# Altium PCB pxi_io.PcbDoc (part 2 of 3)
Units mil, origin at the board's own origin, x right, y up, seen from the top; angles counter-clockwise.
Board outline 6300 x 3935 mil, 2 copper layers (Top Layer, Bottom Layer); 271 components, 388 nets, 1544 pads, 249 vias.
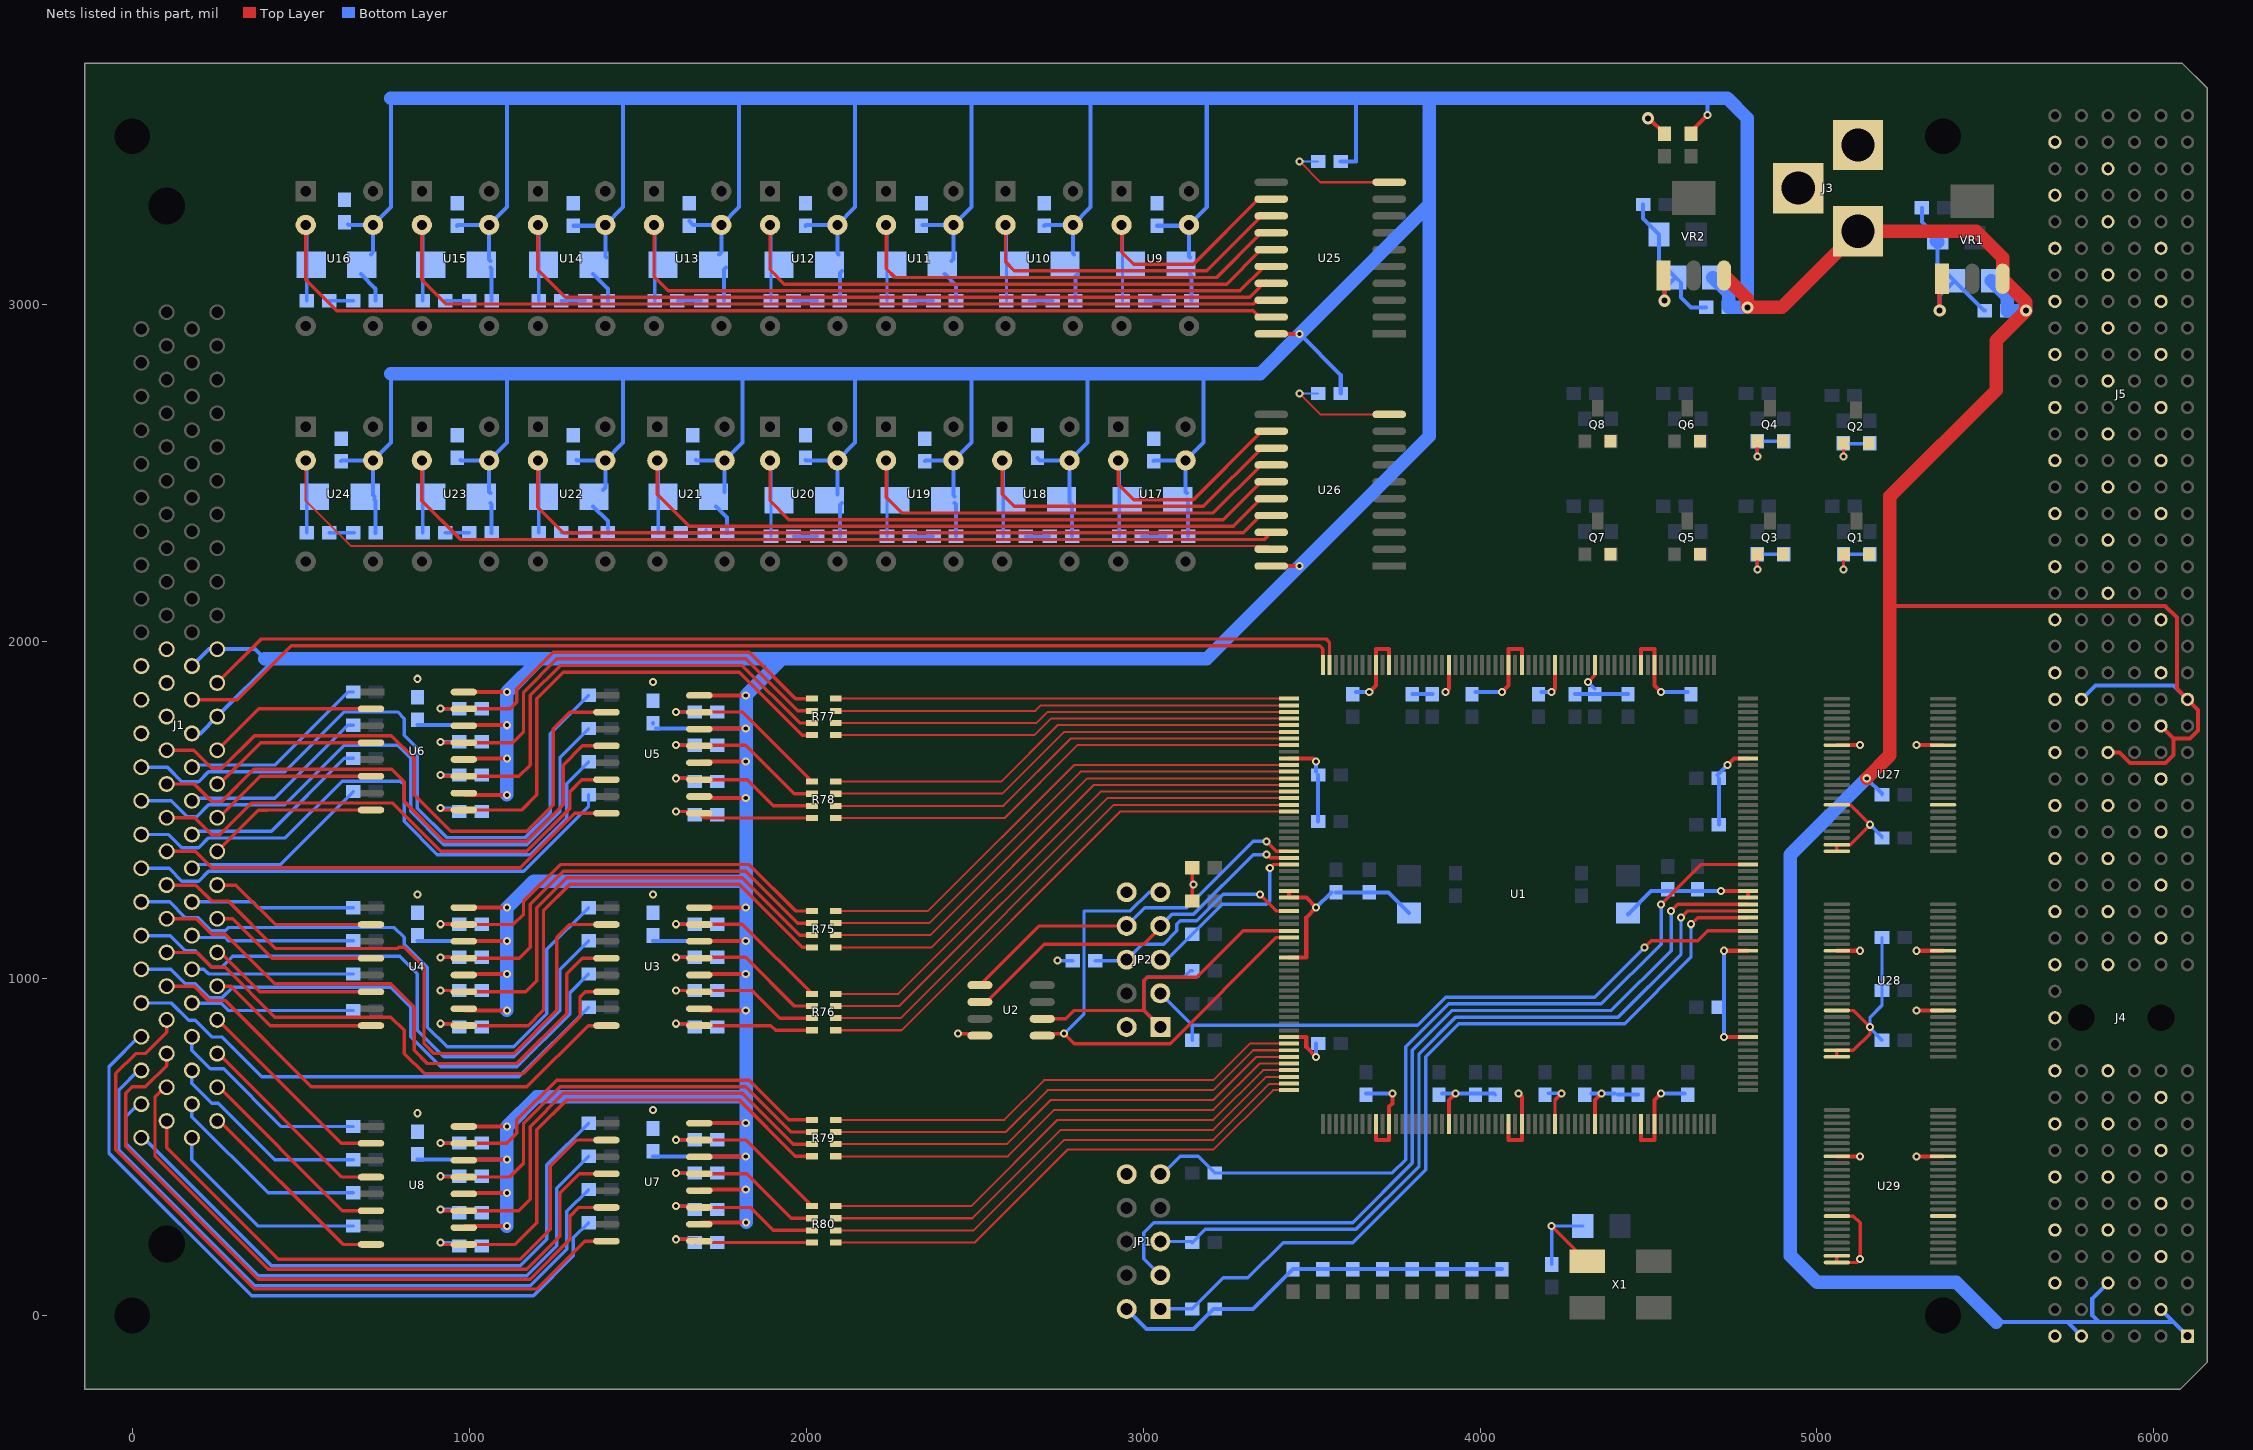
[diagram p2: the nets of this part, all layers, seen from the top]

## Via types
v1: diameter 24, hole 12, Top Layer to Bottom Layer, 241 vias
v2: diameter 36, hole 18, Top Layer to Bottom Layer, 7 vias
v3: diameter 24, hole 12, Top Layer to Bottom Layer, tented bottom, 1 vias

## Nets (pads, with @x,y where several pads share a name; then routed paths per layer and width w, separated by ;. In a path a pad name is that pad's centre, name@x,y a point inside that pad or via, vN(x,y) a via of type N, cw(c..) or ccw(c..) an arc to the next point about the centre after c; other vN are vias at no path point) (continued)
5V: C51.2 C52.2 C53.2 C54.2 C55.2 C56.2 C91.2 C92.2 C93.2 C94.2 C95.2 C96.2 C97.2 C98.2 C99.2 C101.2 C102.2 C103.2 C104.2 C105.2 C106.2 C107.2 C108.2 C109.2 C111.1 C112.2 C115.1 C116.2 D1.2 D2.2 D3.2 D4.2 D5.2 D6.2 D7.2 D8.2 D11.2 D12.2 D13.2 D14.2 D15.2 D16.2 D17.2 D18.2 D19.1 DS9.1 J1.25 J1.26 J1.29 J1.30 J3.1 J4.A1 J4.A25 J4.B2 J4.B24 J4.D3 J4.D23 J4.E1 J4.E25 R81.2 R82.2 R83.2 R84.2 R85.2 R86.2 R87.2 R88.2 R91.2 R92.2 R93.2 R94.2 R95.2 R96.2 R97.2 R98.2 U3.10 U3.12 U3.14 U3.16 U4.10 U4.12 U4.14 U4.16 U5.10 U5.12 U5.14 U5.16 U6.10 U6.12 U6.14 U6.16 U7.10 U7.12 U7.14 U7.16 U8.10 U8.12 U8.14 U8.16 U9.9 U10.9 U11.9 U12.9 U13.9 U14.9 U15.9 U16.9 U17.9 U18.9 U19.9 U20.9 U21.9 U22.9 U23.9 U24.9 U25.20 U26.20 VR1.3 VR2.3 | length 41262.1
  Top Layer w10: DS9.1@4625.98,3507.87 DS9.1@4625.98,3513.78
  Top Layer w12: U8.10@984.25,261.02 988.98,265.75 v1(1112.2,265.75) ; U8.12@984.25,361.02 987.4,364.17 v1(1112.2,364.17) ; U8.14@984.25,461.02 985.83,462.6 v1(1112.2,462.6) ; U8.16@984.25,561.02 v1(1112.2,561.02) ; U4.10@984.25,910.63 989.37,905.51 v1(1112.2,905.51) ; U4.12@984.25,1010.63 987.4,1013.78 v1(1112.2,1013.78) ; U4.14@984.25,1110.63 985.83,1112.2 v1(1112.2,1112.2) ; U4.16@984.25,1210.63 v1(1112.2,1210.63) ; U6.10@984.25,1550.39 989.37,1545.28 v1(1112.2,1545.28) ; U6.12@984.25,1650.39 987.4,1653.54 v1(1112.2,1653.54) ; U6.16@984.25,1850.39 v1(1112.2,1850.39) ; U6.14@985.83,1751.97 v1(1112.2,1751.97) ; U7.10@1683.07,270.87 1688.77,276.57 v1(1821.84,276.57) ; U7.12@1683.07,370.87 1686.22,374.02 v1(1820.87,374.02) ; U7.16@1683.07,570.87 v1(1820.87,570.87) ; U3.10@1683.07,910.63 1688.19,905.51 v1(1820.87,905.51) ; U3.12@1683.07,1010.63 1686.22,1013.78 v1(1820.87,1013.78) ; U3.14@1683.07,1110.63 1684.65,1112.2 v1(1820.87,1112.2) ; U3.16@1683.07,1210.63 v1(1820.87,1210.63) ; U5.10@1683.07,1540.55 1688.19,1535.43 v1(1820.87,1535.43) ; U5.12@1683.07,1640.55 1686.22,1643.7 v1(1820.87,1643.7) ; U5.14@1683.07,1740.55 1684.65,1742.13 v1(1820.87,1742.13) ; U5.16@1683.07,1840.55 v1(1820.87,1840.55) ; U7.14@1684.65,472.44 v1(1820.87,472.44) ; U26.20@3380.31,2224.41 v1(3464.57,2224.41) ; U25.20@3380.31,2913.39 v1(3464.57,2913.39) ; DS9.1@4625.98,3513.78 v1(4675.2,3562.99) ; 5216.54,2106.3 6033.46,2106.3 6067.92,2071.84 6067.92,1860.43 J4.A25@6099.61,1828.74 6131.29,1797.06 6131.29,1736.88 6107.01,1712.6 6058.27,1712.6 ; J4.D23@5863.39,1671.26 5897.32,1671.26 5929,1639.57 6033.99,1639.57 6058.27,1663.85 6058.27,1712.6 ; J4.B24@6020.87,1750 6058.27,1712.6
  Top Layer w40: VR2.3@4724.04,3086.61 4793.31,3017.35 v2(4793.31,2992.13) 4895.93,2992.13 J3.1@5121.74,3217.94 5472.27,3217.94 5550.81,3139.39 VR1.3@5550.81,3076.77 5620.08,3007.5 v2(5620.08,2982.28) 5531.5,2893.7 5531.5,2746.06 5216.54,2431.1 5216.54,2106.3 5216.54,1663.39 v1(5147.64,1594.49)
  Bottom Layer w10: D19.1@5192.91,1545.28 D19.1@5192.91,1549.21 ; v2@5610.24,2982.28 v2(5620.08,2982.28)
  Bottom Layer w12: J1.25@177.17,1727.56 202.17,1727.56 J1.26@252.17,1777.56 423.23,1948.62 ; J1.29@177.17,1927.56 227.95,1978.35 252.17,1978.35 364.17,1978.35 393.7,1948.82 393.7,1942.72 ; C108.2@620.08,2535.43 622.44,2537.8 U24.9@714.96,2537.8 ; C98.2@639.76,3238.19 641.34,3236.61 U16.9@714.96,3236.61 ; D8.2@679.13,3090.55 722.44,3047.24 R88.2@722.44,3011.81 ; D8.2@708.66,3149.61 714.96,3155.91 U16.9@714.96,3236.61 ; D18.2@718.5,2421.26 722.44,2417.32 R98.2@722.44,2322.83 ; D18.2@718.5,2431.1 714.96,2434.65 U24.9@714.96,2537.8 ; 767.72,2795.28 767.72,2590.55 U24.9@714.96,2537.8 ; 767.72,3612.2 767.72,3289.37 U16.9@714.96,3236.61 ; C56.2@846.46,462.6 v1(1112.2,462.6) ; C52.2@846.46,1112.2 v1(1112.2,1112.2) ; C54.2@846.46,1751.97 v1(1112.2,1751.97) ; C97.2@964.57,3234.25 966.93,3236.61 U15.9@1059.45,3236.61 ; C107.2@974.41,2539.37 975.98,2537.8 U23.9@1059.45,2537.8 ; D17.2@1062.99,2411.42 1066.93,2407.48 R97.2@1066.93,2322.83 ; D17.2@1062.99,2440.94 1059.45,2444.49 U23.9@1059.45,2537.8 ; D7.2@1062.99,3110.24 1066.93,3106.3 R87.2@1066.93,3011.81 ; D7.2@1062.99,3129.92 1059.45,3133.47 U15.9@1059.45,3236.61 ; 1112.2,2795.28 1112.2,2590.55 U23.9@1059.45,2537.8 ; 1112.2,3612.2 1112.2,3289.37 U15.9@1059.45,3236.61 ; C96.2@1309.06,3234.25 1401.57,3234.25 U14.9@1403.94,3236.61 ; C106.2@1318.9,2539.37 1320.47,2537.8 U22.9@1403.94,2537.8 ; D16.2@1368.11,2401.57 1411.42,2358.27 R96.2@1411.42,2322.83 ; D6.2@1368.11,3090.55 1411.42,3047.24 R86.2@1411.42,3011.81 ; D16.2@1397.64,2450.79 1403.94,2457.09 U22.9@1403.94,2537.8 ; D6.2@1407.48,3139.76 1403.94,3143.31 U14.9@1403.94,3236.61 ; 1456.69,2795.28 1456.69,2590.55 U22.9@1403.94,2537.8 ; 1456.69,3612.2 1456.69,3289.37 U14.9@1403.94,3236.61 ; C55.2@1545.28,472.44 v1(1820.87,472.44) ; C51.2@1545.28,1112.2 v1(1820.87,1112.2) ; C53.2@1555.12,1742.13 v1(1820.87,1742.13) v1@1821.84,1742.13 ; C95.2@1653.54,3248.03 1664.96,3236.61 U13.9@1748.43,3236.61 ; C105.2@1673.23,2539.37 1674.8,2537.8 U21.9@1758.27,2537.8 ; D15.2@1732.28,2401.57 1765.75,2368.11 R95.2@1765.75,2322.83 ; D5.2@1742.13,3149.61 1748.43,3155.91 U13.9@1748.43,3236.61 ; R85.2@1755.91,3011.81 1755.91,3104.33 D5.2@1761.81,3110.24 ; D15.2@1758.27,2444.49 U21.9@1758.27,2537.8 ; 1801.18,3612.2 1801.18,3289.37 U13.9@1748.43,3236.61 ; 1811.02,2795.28 1811.02,2590.55 U21.9@1758.27,2537.8 ; C104.2@1998.03,2539.37 1999.61,2537.8 U20.9@2092.91,2537.8 ; C94.2@1998.03,3234.25 2000.39,3236.61 U12.9@2092.91,3236.61 ; D14.2@2092.91,2437.4 U20.9@2092.91,2537.8 ; D4.2@2096.46,3149.61 2092.91,3153.15 U12.9@2092.91,3236.61 ; R94.2@2100.39,2312.99 2100.39,2405.51 D14.2@2106.3,2411.42 ; R84.2@2100.39,3011.81 2100.39,3094.49 D4.2@2106.3,3100.39 ; 2145.67,2795.28 2145.67,2590.55 U20.9@2092.91,2537.8 ; 2145.67,3612.2 2145.67,3289.37 U12.9@2092.91,3236.61 ; C93.2@2344.88,3236.61 U11.9@2437.4,3236.61 ; C103.2@2352.36,2535.43 2354.72,2537.8 U19.9@2437.4,2537.8 ; D3.2@2411.42,3090.55 2444.88,3057.09 R83.2@2444.88,3011.81 ; D3.2@2431.1,3129.92 2437.4,3136.22 U11.9@2437.4,3236.61 ; D13.2@2440.94,2411.42 2444.88,2407.48 R93.2@2444.88,2312.99 ; D13.2@2440.94,2431.1 2437.4,2434.65 U19.9@2437.4,2537.8 ; 2490.16,2795.28 2490.16,2590.55 U19.9@2437.4,2537.8 ; 2490.16,3612.2 2490.16,3289.37 U11.9@2437.4,3236.61 ; C102.2@2687.01,2545.28 2694.49,2537.8 U18.9@2781.89,2537.8 ; C92.2@2706.69,3234.25 2709.06,3236.61 U10.9@2791.73,3236.61 ; R92.2@2789.37,2312.99 2789.37,2407.48 2781.89,2414.96 U18.9@2781.89,2537.8 ; D2.2@2795.28,3149.61 2791.73,3153.15 U10.9@2791.73,3236.61 ; R82.2@2799.21,3011.81 2799.21,3084.65 D2.2@2805.12,3090.55 ; 2834.65,2795.28 2834.65,2590.55 U18.9@2781.89,2537.8 ; 2844.49,3612.2 2844.49,3289.37 U10.9@2791.73,3236.61 ; C101.2@3031.5,2535.43 3033.86,2537.8 U17.9@3126.38,2537.8 ; C91.2@3041.34,3234.25 3133.86,3234.25 U9.9@3136.22,3236.61 ; D11.2@3129.92,2421.26 3133.86,2417.32 R91.2@3133.86,2312.99 ; D11.2@3129.92,2440.94 3126.38,2444.49 U17.9@3126.38,2537.8 ; D1.2@3139.76,3090.55 3143.7,3086.61 R81.2@3143.7,3011.81 ; D1.2@3139.76,3139.76 3136.22,3143.31 U9.9@3136.22,3236.61 ; 3179.13,2795.28 3179.13,2590.55 U17.9@3126.38,2537.8 ; 3188.98,3612.2 3188.98,3289.37 U9.9@3136.22,3236.61 ; v1(3464.57,2913.39) 3465.05,2912.9 3586.61,2791.34 C109.2@3586.61,2736.22 ; C99.2@3586.61,3425.2 3631.89,3425.2 3631.89,3612.2 ; v1(4675.2,3562.99) 4675.2,3612.2 ; v1(5147.64,1594.49) D19.1@5192.91,1549.21 ; 5531.5,-19.68 5743.31,-19.68 ; J4.E1@5784.65,-61.02 5743.31,-19.68 ; J4.E25@5784.65,1828.74 5825.98,1870.08 6058.27,1870.08 J4.A25@6099.61,1828.74 ; J4.D3@5863.39,96.46 5816.93,50 5816.93,0 5836.61,-19.68 ; 5984.25,-18.9 5984.25,-19.68 ; J4.B2@6020.87,17.72 6058.27,-19.68 ; J4.A1@6099.61,-61.02 6058.27,-19.68 ; 5743.31,-19.68 5836.61,-19.68 ; 5836.61,-19.68 5984.25,-19.68 ; 5984.25,-19.68 6058.27,-19.68
  Bottom Layer w40: 393.7,1948.82 1210.63,1948.82 ; 767.72,2795.28 1112.2,2795.28 1456.69,2795.28 1811.02,2795.28 2145.67,2795.28 2490.16,2795.28 2834.65,2795.28 3179.13,2795.28 3347.43,2795.28 3465.05,2912.9 3849.4,3297.24 ; 767.72,3612.2 1112.2,3612.2 1456.69,3612.2 1801.18,3612.2 2145.67,3612.2 2490.16,3612.2 2844.49,3612.2 3188.98,3612.2 3849.4,3612.2 ; v1(1112.2,265.75) v1(1112.2,462.6) v1(1112.2,561.02) 1200.79,649.61 1821.84,649.61 ; v1(1112.2,905.51) v1(1112.2,1013.78) v1(1112.2,1112.2) v1(1112.2,1210.63) 1190.94,1289.37 1821.84,1289.37 ; v1(1112.2,1545.28) v1(1112.2,1653.54) v1(1112.2,1751.97) v1(1112.2,1850.39) 1210.63,1948.82 ; v1(1821.84,276.57) 1821.84,472.44 1821.84,649.61 ; C115.1@4690.94,3080.71 4738.19,3033.46 C116.2@4738.19,2992.13 v2(4793.31,2992.13) 4793.31,3553.15 4734.25,3612.2 3849.4,3612.2 ; v1(5147.64,1594.49) 4921.26,1368.11 4921.26,177.17 5000,98.43 5413.39,98.43 5531.5,-19.68 ; C111.1@5517.72,3070.87 5564.96,3023.62 C112.2@5564.96,2982.28 v2(5620.08,2982.28) ; 1210.63,1948.82 1929.13,1948.82 ; 1821.84,649.61 1821.84,1289.37 ; 1821.84,1289.37 1821.84,1742.13 1821.84,1841.53 1929.13,1948.82 ; 1929.13,1948.82 3188.98,1948.82 3849.4,2609.24 3849.4,3297.24 ; 3849.4,3297.24 3849.4,3612.2
ASDO: JP2.9 U1.37 U2.5 | length 1506.9
  Top Layer w10: U2.5@2706.89,836.61 v3(2765.75,836.61) 2795.28,807.09 3080.71,807.09 3395.67,1122.05 U1.37@3433.07,1122.05
  Bottom Layer w10: v3(2765.75,836.61) 2824.8,895.67 2824.8,1200.79 2962.6,1200.79 3018.11,1256.3 JP2.9@3051.18,1256.3
CONF_DONE: JP2.3 R6.2 U1.145 | length 1944.1
  Top Layer w10: v1(4488.19,1092.52) 4507.87,1112.2 4645.67,1112.2 4675.2,1141.73 U1.145@4795.28,1141.73
  Bottom Layer w10: JP2.3@3051.18,956.3 3145.67,861.81 ; R6.2@3145.67,816.93 3145.67,861.81 ; v1(4488.19,1092.52) 4340.55,944.88 3897.64,944.88 3814.57,861.81 3145.67,861.81
DATA: JP2.7 U1.25 U2.2 | length 1105.4
  Top Layer w10: U2.2@2515.75,930.51 2534.84,930.51 2706.69,1102.36 3001.97,1102.36 3051.18,1151.57 JP2.7@3051.18,1156.3 ; v1(3366.14,1368.11) 3375.98,1358.27 U1.25@3433.07,1358.27
  Bottom Layer w10: JP2.7@3051.18,1156.3 3085.83,1190.94 3149.61,1190.94 3326.77,1368.11 v1(3366.14,1368.11)
DC5_CTRL: J1.27 U1.240 | length 3474.2
  Top Layer w10: J1.27@177.17,1827.56 311.81,1827.56 472.44,1988.19 3523.62,1988.19 3533.46,1978.35 U1.240@3533.46,1931.1
DC27_CTRL: J1.28 U1.239 | length 3426
  Top Layer w10: J1.28@252.17,1877.56 382.48,2007.87 3543.31,2007.87 3553.15,1998.03 U1.239@3553.15,1931.1
DCLK: JP2.1 R5.2 U1.36 U2.6 | length 1276.1
  Top Layer w10: U2.6@2700.79,880.51 2770.28,880.51 2795.28,905.51 3001.97,905.51 ; JP2.1@3051.18,856.3 3001.97,905.51 ; U1.36@3433.07,1141.73 3297.24,1141.73 3159.45,1003.94 3011.81,1003.94 3001.97,994.09 3001.97,905.51
  Bottom Layer w10: JP2.1@3051.18,856.3 3001.97,905.51 3001.97,994.09 3011.81,1003.94 3120.08,1003.94 3139.76,1023.62 R5.2@3145.67,1023.62
GND: C1.2 C2.1 C3.2 C5.1 C6.1 C7.2 C9.1 C10.1 C11.1 C12.1 C13.1 C14.1 C15.1 C16.1 C17.1 C18.1 C19.1 C20.1 C21.1 C22.1 C31.1 C32.1 C33.1 C34.1 C35.1 C36.1 C37.1 C38.1 C39.1 C40.1 C41.1 C42.1 C51.1 C52.1 C53.1 C54.1 C55.1 C56.1 C91.1 C92.1 C93.1 C94.1 C95.1 C96.1 C97.1 C98.1 C99.1 C101.1 C102.1 C103.1 C104.1 C105.1 C106.1 C107.1 C108.1 C109.1 C111.2 C112.1 C113.2 C114.1 C115.2 C116.1 C117.2 C118.1 C120.1 C121.1 C123.1 J1.75 J1.76 J1.77 J1.78 J1.79 J1.80 J3.2 J3.3 J4.B4 J4.B6 J4.B8 J4.B10 J4.B16 J4.B18 J4.B20 J4.B22 J4.D5 J4.D7 J4.D9 J4.D11 J4.D15 J4.D17 J4.D19 J4.D21 J4.F1 J4.F3 J4.F5 J4.F7 J4.F9 J4.F11 J4.F13 J4.F15 J4.F17 J4.F19 J4.F21 J4.F23 J4.F25 J5.B1 J5.B3 J5.B7 J5.B9 J5.B11 J5.B13 J5.B15 J5.B17 J5.D4 J5.D6 J5.D8 J5.D10 J5.D12 J5.D14 J5.D16 J5.D18 J5.D20 J5.F1 J5.F3 J5.F5 J5.F7 J5.F9 J5.F11 J5.F13 J5.F15 J5.F17 J5.F19 J5.F21 JP1.2 JP1.10 JP2.2 JP2.10 Q1.3 Q2.3 Q3.3 Q4.3 Q5.3 Q6.3 Q7.3 Q8.3 R3.2 R4.1 R9.2 R10.2 R15.2 R16.2 R17.2 R18.2 R23.2 R24.2 R25.2 R26.2 R31.2 R32.2 R33.2 R34.2 R39.2 R40.2 R41.2 R42.2 R55.2 R56.2 R57.2 R58.2 R71.2 R72.2 R73.2 R74.2 R116.1 R120.2 R121.2 R122.2 R123.2 R124.2 R125.2 R126.2 R127.2 R140.1 U1.10 U1.30 U1.31 U1.40 U1.52 U1.69 U1.71 U1.80 U1.89 U1.91 U1.96 U1.102 U1.109 U1.111 U1.129 U1.142 U1.150 U1.151 U1.171 U1.190 U1.192 U1.199 U1.205 U1.210 U1.212 U1.221 U1.230 U1.232 U2.4 U25.10 U26.10 U27.8 U27.17 U27.32 U27.41 U27.47 U27.48 U28.8 U28.17 U28.32 U28.41 U28.47 U28.48 U29.8 U29.17 U29.32 U29.41 U29.47 U29.48 VR1.1 VR2.1 X1.2 | length 10385.4
  Top Layer w6: v1(3464.57,2736.22) 3526.38,2674.41 U26.10@3730.31,2674.41 ; v1(3464.57,3425.2) 3526.38,3363.39 U25.10@3730.31,3363.39
  Top Layer w10: v1(2450.79,836.61) 2509.65,836.61 U2.4@2515.75,830.51 ; R10.2@3145.67,1230.32 3145.67,1275.59 v1(3149.61,1279.53) 3145.67,1283.46 R9.2@3145.67,1328.74 ; v1(4212.6,265.75) 4317.24,161.1 X1.2@4318.13,161.1 ; U1.96@4222.44,568.9 4222.44,639.76 v1(4242.13,659.45) ; v1(4320.87,1879.92) 4340.55,1899.61 U1.199@4340.55,1931.1 ; J3.3@4904.64,3385.83 J3.3@4944.57,3345.89 ; U29.47@5059.06,177.17 U29.48@5059.06,157.48 5118.11,157.48 v1(5127.95,167.32) 5127.95,275.59 5108.27,295.28 U29.41@5059.06,295.28 ; U28.48@5059.06,767.72 U28.47@5059.06,787.4 5108.27,787.4 5157.48,836.61 v1(5157.48,856.3) 5108.27,905.51 U28.41@5059.06,905.51 ; U27.48@5059.06,1377.95 U27.47@5059.06,1397.64 5098.43,1397.64 v1(5157.48,1456.69) 5118.11,1496.06 ; U27.41@5059.06,1515.75 5098.43,1515.75 5118.11,1496.06 ; 5119.08,1497.03 5118.11,1496.06
  Top Layer w12: U1.52@3433.07,826.77 3484.25,826.77 3484.25,797.24 v1(3513.78,767.72) ; U1.40@3433.07,1062.99 3484.25,1062.99 3484.25,1181.1 v1(3513.78,1210.63) 3484.25,1240.16 U1.31@3433.07,1240.16 U1.30@3433.07,1259.84 ; U1.10@3433.07,1653.54 3503.94,1653.54 v1(3513.78,1643.7) ; v1(3671.26,1850.39) 3690.94,1870.08 U1.232@3690.94,1931.1 3690.94,1978.35 3730.31,1978.35 U1.230@3730.31,1931.1 ; U1.69@3690.94,568.9 3690.94,521.65 3730.31,521.65 U1.71@3730.31,568.9 3730.31,620.08 3740.16,629.92 v1(3740.16,659.45) ; v1(3897.64,1850.39) 3907.48,1860.24 U1.221@3907.48,1931.1 ; U1.80@3907.48,568.9 3907.48,639.76 v1(3927.17,659.45) ; v1(4064.96,1850.39) 4084.65,1870.08 U1.212@4084.65,1931.1 4084.65,1978.35 4124.02,1978.35 U1.210@4124.02,1931.1 ; U1.89@4084.65,568.9 4084.65,521.65 4124.02,521.65 U1.91@4124.02,568.9 4124.02,649.61 v1(4114.17,659.45) ; v1(4212.6,1850.39) 4222.44,1860.24 U1.205@4222.44,1931.1 ; U1.102@4340.55,568.9 4340.55,639.76 v1(4360.24,659.45) ; U1.109@4478.35,568.9 4478.35,521.65 4517.72,521.65 U1.111@4517.72,568.9 4517.72,639.76 v1(4537.4,659.45) ; U1.192@4478.35,1931.1 4478.35,1978.35 4517.72,1978.35 U1.190@4517.72,1931.1 4517.72,1870.08 v1(4537.4,1850.39) ; v2(4498.03,3553.15) 4501.97,3553.15 R140.1@4547.24,3507.87 ; v2(4547.24,3011.81) VR2.1@4547.24,3051.18 ; v1(4714.57,1259.84) U1.151@4795.28,1259.84 U1.150@4795.28,1240.16 ; v1(4724.41,826.77) U1.129@4795.28,826.77 ; v1(4724.41,1082.68) U1.142@4795.28,1082.68 ; v1(4734.25,1633.86) 4753.94,1653.54 U1.171@4795.28,1653.54 ; U29.32@5059.06,472.44 v1(5127.95,472.44) ; U28.32@5059.06,1082.68 v1(5127.95,1082.68) ; U27.32@5059.06,1692.91 v1(5127.95,1692.91) ; v1(5295.28,472.44) U29.17@5374.02,472.44 ; v1(5295.28,905.51) U28.8@5374.02,905.51 ; v1(5295.28,1082.68) U28.17@5374.02,1082.68 ; v1(5295.28,1692.91) U27.17@5374.02,1692.91 ; v2(5364.17,2982.28) VR1.1@5364.17,3070.13
  Top Layer w40: J3.2@5121.74,3467.57 J3.2@5121.74,3473.84
  Bottom Layer w6: v1(3464.57,2736.22) C109.1@3519.69,2736.22 ; v1(3464.57,3425.2) C99.1@3519.69,3425.2
  Bottom Layer w10: v1(2746.06,1053.15) R4.1@2791.34,1053.15 ; C18.1@4041.34,659.45 C18.1@4045.28,655.51 ; C38.1@4202.76,659.45 v1(4242.13,659.45) ; C2.1@4212.6,151.57 v1(4212.6,265.75) C1.2@4305.12,265.75 ; v1(4320.87,1879.92) C15.1@4340.55,1860.24 ; C115.2@4580.71,3080.71 C115.2@4596.46,3064.96 ; v1(5157.48,1456.69) 5192.91,1421.26 R116.1@5192.91,1417.32 ; C120.1@5192.91,816.93 5157.48,852.36 v1(5157.48,856.3) 5157.48,885.83 5192.91,921.26 C121.1@5192.91,964.57 C123.1@5192.91,1122.05 ; C111.2@5407.48,3070.87 C111.2@5423.23,3055.12
  Bottom Layer w12: JP1.2@2951.18,19.68 3010.24,-39.37 3149.61,-39.37 3208.66,19.68 R3.2@3212.6,19.68 3326.77,19.68 R127.2@3444.88,137.8 R126.2@3533.46,137.8 R125.2@3622.05,137.8 R124.2@3710.63,137.8 R123.2@3799.21,137.8 R122.2@3887.8,137.8 R121.2@3976.38,137.8 R120.2@4064.96,137.8 ; v1(3513.78,767.72) C40.1@3513.78,807.09 ; v1(3513.78,1210.63) C6.1@3559.06,1255.91 ; C42.1@3513.78,1614.17 v1(3513.78,1643.7) ; C41.1@3519.69,1466.54 C42.1@3519.69,1604.33 ; C6.1@3572.83,1255.91 C5.1@3671.26,1255.91 3728.35,1255.91 C3.2@3789.37,1194.88 ; C31.1@3631.89,1850.39 v1(3671.26,1850.39) ; C39.1@3661.42,659.45 v1(3740.16,659.45) ; C11.1@3799.21,1844.49 C12.1@3858.27,1844.49 ; C17.1@3887.8,659.45 v1(3927.17,659.45) C18.1@4041.34,659.45 ; C13.1@3986.22,1850.39 v1(4064.96,1850.39) ; C32.1@4183.07,1850.39 v1(4212.6,1850.39) ; C14.1@4281.5,1844.49 C15.1@4340.55,1844.49 C16.1@4438.98,1844.49 ; 4330.71,659.45 v1(4360.24,659.45) C21.1@4399.61,659.45 ; C21.1@4409.45,655.51 C22.1@4468.5,655.51 ; C7.2@4438.98,1190.94 4507.87,1259.84 v1(4714.57,1259.84) ; C118.1@4484.25,3297.24 4484.25,3255.91 C117.2@4531.5,3208.66 4531.5,3129.92 C115.2@4580.71,3080.71 4547.24,3047.24 v2(4547.24,3011.81) ; v1(4537.4,659.45) C37.1@4606.3,659.45 ; v1(4537.4,1850.39) C33.1@4616.14,1850.39 ; C115.2@4596.46,3064.96 4596.46,3021.65 4625.98,2992.13 C116.1@4671.26,2992.13 ; C34.1@4704.72,1604.33 v1(4734.25,1633.86) ; C35.1@4708.66,1456.69 C34.1@4708.66,1594.49 ; v1(4724.41,826.77) 4724.41,905.51 v1(4724.41,1082.68) ; C114.1@5311.02,3287.4 5311.02,3246.06 C113.2@5358.27,3198.82 ; C113.2@5358.27,3185.04 5358.27,3120.08 C111.2@5407.48,3070.87 ; v2(5364.17,2982.28) 5364.17,3027.56 C111.2@5407.48,3070.87 ; C112.1@5498.03,2982.28 5496.06,2982.28 C111.2@5407.48,3070.87
  Bottom Layer w40: J3.2@5121.74,3473.84 J3.2@5124.58,3473.84 ; C113.2@5354.33,3188.98 C113.2@5358.27,3185.04
  other v1: 846.46,600.39 1545.28,610.24 846.46,1250 1545.28,1250 1545.28,1879.92 846.46,1889.76
GND_I5_1: J1.60 U3.8 | length 1504.1
  Top Layer w10: J1.60@102.17,977.56 183.86,977.56 226.38,935.04 275.59,935.04 531.5,679.13 1171.26,679.13 1352.76,860.63 U3.8@1407.48,860.63
GND_I5_2: J1.62 U3.6 | length 1629.3
  Top Layer w10: J1.62@102.17,1077.56 192.13,1077.56 236.22,1033.46 275.59,1033.46 423.23,885.83 767.72,885.83 807.09,846.46 807.09,777.56 866.14,718.5 1161.42,718.5 1328.74,885.83 1328.74,944.88 1344.49,960.63 U3.6@1407.48,960.63
GND_I5_3: J1.64 U3.4 | length 1756.9
  Top Layer w10: J1.64@102.17,1177.56 190.55,1177.56 236.22,1131.89 275.59,1131.89 423.23,984.25 767.72,984.25 836.61,915.35 836.61,787.4 875.98,748.03 1141.73,748.03 1289.37,895.67 1289.37,1013.78 1336.22,1060.63 U3.4@1407.48,1060.63
GND_I5_4: J1.66 U3.2 | length 1933.3
  Top Layer w10: J1.66@102.17,1277.56 188.98,1277.56 236.22,1230.32 285.43,1230.32 426.54,1089.2 787.09,1089.2 790.4,1092.52 807.09,1092.52 866.14,1033.46 866.14,807.09 895.67,777.56 1131.89,777.56 1259.84,905.51 1259.84,1122.05 1298.43,1160.63 U3.2@1407.48,1160.63
GND_I5_5: J1.10 U4.8 | length 504.9
  Top Layer w10: J1.10@252.17,977.56 292.13,977.56 409.05,860.63 U4.8@708.66,860.63
GND_I5_6: J1.12 U4.6 | length 502.3
  Top Layer w10: J1.12@256.59,1081.99 377.95,960.63 U4.6@708.66,960.63
GND_I5_7: J1.14 U4.4 | length 504.9
  Top Layer w10: J1.14@252.17,1177.56 298.82,1177.56 415.75,1060.63 U4.4@708.66,1060.63
GND_I5_8: J1.16 U4.2 | length 504.9
  Top Layer w10: J1.16@252.17,1277.56 307.09,1277.56 424.02,1160.63 U4.2@708.66,1160.63
GND_I5_9: J1.68 U5.8 | length 1392.6
  Top Layer w10: J1.68@102.17,1377.56 187.4,1377.56 236.22,1328.74 1151.57,1328.74 1313.39,1490.55 U5.8@1407.48,1490.55
GND_I5_10: J1.70 U5.6 | length 1541.4
  Top Layer w10: J1.70@102.17,1477.56 185.83,1477.56 236.22,1427.17 260.26,1427.17 354.33,1521.24 772.07,1521.24 915.35,1377.95 1171.26,1377.95 1299.21,1505.91 1299.21,1555.12 1334.65,1590.55 U5.6@1407.48,1590.55
GND_I5_11: J1.72 U5.4 | length 1676
  Top Layer w10: J1.72@102.17,1577.56 184.25,1577.56 236.22,1525.59 265.75,1525.59 361.39,1621.24 770.5,1621.24 807.09,1584.65 807.09,1525.59 925.2,1407.48 1171.26,1407.48 1279.53,1515.75 1279.53,1633.86 1336.22,1690.55 U5.4@1407.48,1690.55
GND_I5_12: J1.74 U5.2 | length 1828
  Top Layer w10: J1.74@102.17,1677.56 182.68,1677.56 236.22,1624.02 265.75,1624.02 362.97,1721.24 768.92,1721.24 836.61,1653.54 836.61,1545.28 944.88,1437.01 1171.26,1437.01 1250,1515.75 1250,1742.13 1298.43,1790.55 U5.2@1407.48,1790.55
GND_I5_13: J1.18 U6.8 | length 507.4
  Top Layer w10: J1.18@252.17,1377.56 374.35,1499.75 400.33,1499.75 400.97,1500.39 U6.8@708.66,1500.39
GND_I5_14: J1.20 U6.6 | length 508.8
  Top Layer w10: J1.20@249.7,1480.02 259.55,1480.02 379.92,1600.39 U6.6@708.66,1600.39
GND_I5_15: J1.22 U6.4 | length 500.9
  Top Layer w10: J1.22@258.66,1577.56 381.5,1700.39 U6.4@708.66,1700.39
GND_I5_16: J1.24 U6.2 | length 507.4
  Top Layer w10: J1.24@252.17,1677.56 375,1800.39 U6.2@708.66,1800.39
GND_I27_1: J1.58 U7.8 | length 2152.2
  Top Layer w10: J1.58@102.17,877.56 102.17,840.35 39.37,777.56 9.84,777.56 -49.21,718.5 -49.21,492.13 364.17,78.74 1200.79,78.74 1342.91,220.87 U7.8@1407.48,220.87
GND_I27_2: J1.56 U7.6 | length 2067.8
  Top Layer w10: J1.56@102.17,777.56 102.17,741.93 39.37,679.13 0,679.13 -19.68,659.45 -19.68,501.97 374.02,108.27 1181.1,108.27 1299.21,226.38 1299.21,295.28 1324.8,320.87 U7.6@1407.48,320.87
GND_I27_3: J1.54 U7.4 | length 1894.7
  Top Layer w10: J1.54@102.17,682.87 67.54,648.25 67.54,473.8 403.54,137.8 1171.26,137.8 1269.68,236.22 1269.68,364.17 1326.38,420.87 U7.4@1407.48,420.87
GND_I27_4: J1.52 U7.2 | length 1777.7
  Top Layer w10: J1.52@102.17,577.56 102.17,498.23 433.07,167.32 1151.57,167.32 1240.16,255.91 1240.16,442.91 1318.11,520.87 U7.2@1407.48,520.87
GND_I27_5: J1.2 U8.8 | length 611.2
  Top Layer w10: J1.2@252.17,584.45 625.59,211.02 U8.8@708.66,211.02
GND_I27_6: J1.4 U8.6 | length 610.5
  Top Layer w10: J1.4@252.17,682.87 624.02,311.02 U8.6@708.66,311.02
GND_I27_7: J1.6 U8.4 | length 609.9
  Top Layer w10: J1.6@252.17,781.3 622.44,411.02 U8.4@708.66,411.02
GND_I27_8: J1.8 U8.2 | length 609.2
  Top Layer w10: J1.8@252.17,879.72 620.87,511.02 U8.2@708.66,511.02
I5_1: J1.59 R11.1 | length 1503.5
  Bottom Layer w10: J1.59@27.17,927.56 115.75,927.56 167.32,875.98 187.01,875.98 236.22,826.77 265.75,826.77 383.86,708.66 1147.64,708.66 R11.1@1354.33,915.35
I5_2: J1.61 R12.1 | length 1676
  Bottom Layer w10: J1.61@27.17,1027.56 114.17,1027.56 157.48,984.25 187.01,984.25 228.32,942.94 266.51,942.94 297.98,974.41 767.72,974.41 826.77,915.35 826.77,826.77 915.35,738.19 1141.73,738.19 1299.21,895.67 1299.21,958.66 R12.1@1354.33,1013.78
I5_3: J1.63 R13.1 | length 1815.8
  Bottom Layer w10: J1.63@27.17,1127.56 112.6,1127.56 157.48,1082.68 187.01,1082.68 236.22,1033.46 265.75,1033.46 298.84,1066.56 793.68,1066.56 846.46,1013.78 846.46,846.46 925.2,767.72 1131.89,767.72 1269.68,905.51 1269.68,1027.56 R13.1@1354.33,1112.2
I5_4: J1.65 R14.1 | length 1912
  Bottom Layer w10: J1.65@27.17,1227.56 111.02,1227.56 157.48,1181.1 195.46,1181.1 234.83,1141.73 275.59,1141.73 285.43,1151.57 777.56,1151.57 807.09,1122.05 807.09,1102.36 875.98,1033.46 875.98,856.3 935.04,797.24 1131.89,797.24 1230.32,895.67 1230.32,1086.61 R14.1@1354.33,1210.63
I5_5: J1.9 R19.1 | length 487.5
  Bottom Layer w10: J1.9@177.17,927.56 177.79,926.94 264.01,926.94 285.43,905.51 R19.1@655.51,905.51
I5_6: J1.11 R20.1 | length 484.9
  Bottom Layer w10: J1.11@177.79,1026.94 J1.11@177.17,1027.56 212.6,1027.56 226.38,1013.78 R20.1@655.51,1013.78
I5_7: J1.13 R21.1 | length 484.7
  Bottom Layer w10: J1.13@177.17,1127.56 182.68,1122.05 275.59,1122.05 285.43,1112.2 R21.1@655.51,1112.2
I5_8: J1.15 R22.1 | length 485.4
  Bottom Layer w10: J1.15@177.17,1227.56 357.09,1227.56 374.02,1210.63 R22.1@655.51,1210.63
I5_9: J1.67 R27.1 | length 1468.6
  Bottom Layer w10: J1.67@27.17,1327.56 109.45,1327.56 147.64,1289.37 196.85,1289.37 226.38,1318.9 1161.42,1318.9 1354.33,1511.81 R27.1@1354.33,1545.28
I5_10: J1.69 R28.1 | length 1753.4
  Bottom Layer w10: J1.69@27.17,1427.56 107.87,1427.56 147.64,1387.8 196.85,1387.8 226.38,1417.32 454.38,1417.32 622.86,1585.8 796.09,1585.8 807.09,1574.8 807.09,1466.54 905.51,1368.11 1181.1,1368.11 1289.37,1476.38 1289.37,1578.74 R28.1@1354.33,1643.7
I5_11: J1.71 R29.1 | length 1886.3
  Bottom Layer w10: J1.71@27.17,1527.56 116.14,1527.56 163.02,1480.68 191.31,1480.68 226.38,1515.75 452.76,1515.75 629.92,1692.91 787.4,1692.91 826.77,1653.54 826.77,1496.06 925.2,1397.64 1171.26,1397.64 1269.68,1496.06 1269.68,1657.48 R29.1@1354.33,1742.13
I5_12: J1.73 R30.1 | length 2029.2
  Bottom Layer w10: J1.73@27.17,1627.56 104.72,1627.56 147.64,1584.65 196.85,1584.65 226.38,1614.17 452.76,1614.17 629.92,1791.34 787.4,1791.34 807.09,1771.65 807.09,1722.44 846.46,1683.07 846.46,1505.91 933.57,1418.79 1166.57,1418.79 1240.16,1492.38 1240.16,1726.38 R30.1@1354.33,1840.55
I5_13: J1.17 R35.1 | length 555.4
  Bottom Layer w10: J1.17@189.76,1338.58 438.98,1338.58 R35.1@655.51,1555.12
I5_14: J1.19 R36.1 | length 572
  Bottom Layer w10: J1.19@177.17,1427.56 186.61,1437.01 413.39,1437.01 629.92,1653.54 R36.1@655.51,1653.54
I5_15: J1.21 R37.1 | length 554.3
  Bottom Layer w10: J1.21@190.94,1535.43 423.23,1535.43 639.76,1751.97 R37.1@655.51,1751.97
I5_16: J1.23 R38.1 | length 570.6
  Bottom Layer w10: J1.23@177.17,1627.56 183.46,1633.86 423.23,1633.86 639.76,1850.39 R38.1@655.51,1850.39
I5_D1: R76.5 U1.18 | length 1614.2
  Top Layer w6: R76.5@2087.87,846.72 2283.73,846.72 2933.07,1496.06 U1.18@3433.07,1496.06
I5_D1_R: R15.1 R76.4 U3.9 | length 470.6
  Top Layer w10: v1(1614.17,866.14) 1677.56,866.14 U3.9@1683.07,860.63 1895.28,860.63 1909.18,846.72 R76.4@2017.72,846.72
  Bottom Layer w10: v1(1614.17,866.14) R15.1@1673.23,866.14
I5_D2: R76.6 U1.17 | length 1607.4
  Top Layer w6: R76.6@2087.87,882.72 2280.36,882.72 2913.39,1515.75 U1.17@3433.07,1515.75
I5_D2_R: R16.1 R76.3 U3.11 | length 492.6
  Top Layer w10: v1(1614.17,964.57) 1683.07,964.57 1840.55,964.57 1922.39,882.72 R76.3@2017.72,882.72
  Bottom Layer w10: v1(1614.17,964.57) R16.1@1669.29,964.57
I5_D3: R76.7 U1.16 | length 1600.6
  Top Layer w6: R76.7@2087.87,918.72 2276.99,918.72 2893.7,1535.43 U1.16@3433.07,1535.43
I5_D3_R: R17.1 R76.2 U3.13 | length 521.8
  Top Layer w10: v1(1614.17,1062.99) U3.13@1680.71,1062.99 ; U3.13@1683.07,1060.63 U3.13@1680.71,1062.99 ; R76.2@2017.72,918.72 1965.13,918.72 1820.87,1062.99 U3.13@1680.71,1062.99
  Bottom Layer w10: v1(1614.17,1062.99) R17.1@1669.29,1062.99
I5_D4: R76.8 U1.15 | length 1593.9
  Top Layer w6: R76.8@2087.87,954.72 2273.62,954.72 2874.02,1555.12 U1.15@3433.07,1555.12
I5_D4_R: R18.1 R76.1 U3.15 | length 545.4
  Top Layer w10: v1(1614.17,1161.42) U3.15@1682.28,1161.42 ; U3.15@1683.07,1160.63 U3.15@1682.28,1161.42 ; R76.1@2017.72,954.72 1811.02,1161.42 U3.15@1682.28,1161.42
  Bottom Layer w10: v1(1614.17,1161.42) R18.1@1669.29,1161.42
I5_D5: R75.5 U1.14 | length 1544.9
  Top Layer w6: R75.5@2087.87,1092.79 2372.32,1092.79 2854.33,1574.8 U1.14@3433.07,1574.8
I5_D5_R: R23.1 R75.4 U4.9 | length 1575.5
  Top Layer w10: v1(915.35,866.14) U4.9@974.41,866.14 ; U4.9@984.25,860.63 1175.59,860.63 1220.47,905.51 1220.47,1200.79 1299.21,1279.53 1801.18,1279.53 1987.92,1092.79 R75.4@2017.72,1092.79
  Bottom Layer w10: v1(915.35,866.14) 960.63,866.14 R23.1@970.47,856.3
I5_D6: R75.6 U1.13 | length 1538.1
  Top Layer w6: R75.6@2087.87,1128.79 2368.94,1128.79 2834.65,1594.49 U1.13@3433.07,1594.49
I5_D6_R: R24.1 R75.3 U4.11 | length 1496.8
  Top Layer w10: v1(915.35,964.57) 980.32,964.57 U4.11@984.25,960.63 1167.32,960.63 1200.79,994.09 1200.79,1210.63 1289.37,1299.21 1811.02,1299.21 1981.45,1128.79 R75.3@2017.72,1128.79
  Bottom Layer w10: v1(915.35,964.57) R24.1@970.47,964.57
I5_D7: R75.7 U1.12 | length 1531.3
  Top Layer w6: R75.7@2087.87,1164.79 2365.57,1164.79 2814.96,1614.17 U1.12@3433.07,1614.17
I5_D7_R: R25.1 R75.2 U4.13 | length 1404.2
  Top Layer w10: v1(915.35,1062.99) 981.89,1062.99 U4.13@984.25,1060.63 1149.21,1060.63 1181.1,1092.52 1181.1,1220.47 1279.53,1318.9 1820.87,1318.9 1974.98,1164.79 R75.2@2017.72,1164.79
  Bottom Layer w10: v1(915.35,1062.99) R25.1@970.47,1062.99
I5_D8: R75.8 U1.11 | length 1524.6
  Top Layer w6: R75.8@2087.87,1200.79 2362.2,1200.79 2795.28,1633.86 U1.11@3433.07,1633.86
I5_D8_R: R26.1 R75.1 U4.15 | length 1311.7
  Top Layer w10: v1(915.35,1161.42) 983.46,1161.42 U4.15@984.25,1160.63 1131.1,1160.63 1161.42,1190.94 1161.42,1230.31 1269.69,1338.58 1830.71,1338.58 1968.5,1200.79 R75.1@2017.72,1200.79
  Bottom Layer w10: v1(915.35,1161.42) R26.1@970.47,1161.42
I5_D9: R78.5 U1.8 | length 1434.8
  Top Layer w6: R78.5@2087.87,1476.65 2588.85,1476.65 2805.12,1692.91 U1.8@3433.07,1692.91
I5_D9_R: R31.1 R78.4 U5.9 | length 456.9
  Top Layer w10: v1(1614.17,1496.06) 1677.56,1496.06 U5.9@1683.07,1490.55 1696.98,1476.65 R78.4@2017.72,1476.65
  Bottom Layer w10: v1(1614.17,1496.06) R31.1@1659.45,1496.06
I5_D10: R78.6 U1.7 | length 1428
  Top Layer w6: R78.6@2087.87,1512.65 2585.48,1512.65 2785.43,1712.6 U1.7@3433.07,1712.6
I5_D10_R: R32.1 R78.3 U5.11 | length 496.6
  Top Layer w10: v1(1614.17,1594.49) 1679.13,1594.49 U5.11@1683.07,1590.55 1824.8,1590.55 1902.71,1512.65 R78.3@2017.72,1512.65
  Bottom Layer w10: v1(1614.17,1594.49) 1659.45,1594.49 R32.1@1669.29,1584.65
I5_D11: R78.7 U1.6 | length 1421.3
  Top Layer w6: R78.7@2087.87,1548.65 2582.11,1548.65 2765.75,1732.28 U1.6@3433.07,1732.28
I5_D11_R: R33.1 R78.2 U5.13 | length 521.8
  Top Layer w10: v1(1614.17,1692.91) U5.13@1680.71,1692.91 ; U5.13@1683.07,1690.55 U5.13@1680.71,1692.91 ; R78.2@2017.72,1548.65 1965.13,1548.65 1820.87,1692.91 U5.13@1680.71,1692.91
  Bottom Layer w10: v1(1614.17,1692.91) R33.1@1669.29,1692.91
I5_D12: R78.8 U1.5 | length 1414.5
  Top Layer w6: R78.8@2087.87,1584.65 2578.74,1584.65 2746.06,1751.97 U1.5@3433.07,1751.97
I5_D12_R: R34.1 R78.1 U5.15 | length 545.4
  Top Layer w10: v1(1614.17,1791.34) U5.15@1682.28,1791.34 ; U5.15@1683.07,1790.55 U5.15@1682.28,1791.34 ; R78.1@2017.72,1584.65 1811.02,1791.34 U5.15@1682.28,1791.34
  Bottom Layer w10: v1(1614.17,1791.34) R34.1@1669.29,1791.34
I5_D13: R77.5 U1.4 | length 1365.5
  Top Layer w6: R77.5@2087.87,1722.71 2677.43,1722.71 2726.38,1771.65 U1.4@3433.07,1771.65
I5_D13_R: R39.1 R77.4 U6.9 | length 1577.9
  Top Layer w10: v1(915.35,1505.91) 920.87,1500.39 U6.9@984.25,1500.39 1155.91,1500.39 1200.79,1545.28 1200.79,1830.71 1279.53,1909.45 1801.18,1909.45 1988.19,1722.44 R77.4@2017.72,1722.44
  Bottom Layer w10: v1(915.35,1505.91) 960.63,1505.91 R39.1@970.47,1496.06
I5_D14: R77.6 U1.3 | length 1358.7
  Top Layer w6: R77.6@2087.87,1758.71 2683.91,1758.71 2716.54,1791.34 U1.3@3433.07,1791.34
I5_D14_R: R40.1 R77.3 U6.11 | length 1486.9
  Top Layer w10: v1(915.35,1604.33) 919.29,1600.39 U6.11@984.25,1600.39 1147.64,1600.39 1181.1,1633.86 1181.1,1840.55 1269.69,1929.13 1811.02,1929.13 1981.45,1758.71 R77.3@2017.72,1758.71
  Bottom Layer w10: v1(915.35,1604.33) R40.1@970.47,1604.33
I5_D15: R77.7 U1.2 | length 1352
  Top Layer w6: R77.7@2087.87,1794.71 2680.54,1794.71 2696.85,1811.02 U1.2@3433.07,1811.02
I5_D15_R: R41.1 R77.2 U6.13 | length 1394.4
  Top Layer w10: v1(915.35,1702.76) 917.72,1700.39 U6.13@984.25,1700.39 1129.53,1700.39 1161.42,1732.28 1161.42,1850.39 1259.84,1948.82 1820.87,1948.82 1974.98,1794.71 R77.2@2017.72,1794.71
  Bottom Layer w10: v1(915.35,1702.76) R41.1@970.47,1702.76
I5_D16: R77.8 U1.1 | length 1335.4
  Top Layer w6: R77.8@2097.72,1830.71 U1.1@3433.07,1830.71
I5_D16_R: R42.1 R77.1 U6.15 | length 1307.6
  Top Layer w10: v1(915.35,1801.18) 916.14,1800.39 U6.15@984.25,1800.39 1121.26,1800.39 1141.73,1820.87 1141.73,1860.24 1250,1968.5 1830.71,1968.5 1968.5,1830.71 R77.1@2017.72,1830.71
  Bottom Layer w10: v1(915.35,1801.18) R42.1@970.47,1801.18
I27_1: J1.57 R45.1 | length 2111.1
  Bottom Layer w10: J1.57@27.17,834.25 -68.9,738.19 -68.9,482.28 354.33,59.06 1190.94,59.06 1309.06,177.17 1309.06,230.31 R45.1@1354.33,275.59
I27_2: J1.55 R48.1 | length 2010.2
  Bottom Layer w10: J1.55@23.03,731.69 -39.37,669.29 -39.37,492.13 364.17,88.58 1181.1,88.58 1289.37,196.85 1289.37,309.06 R48.1@1354.33,374.02
I27_3: J1.53 R51.1 | length 1922.6
  Bottom Layer w10: J1.53@12.8,636.81 12.8,623.03 -19.68,590.55 -19.68,511.81 374.02,118.11 1171.26,118.11 1259.84,206.69 1259.84,377.95 R51.1@1354.33,472.44
I27_4: J1.51 R54.1 | length 1787.5
  Bottom Layer w10: J1.51@27.17,524.02 37.01,524.02 413.39,147.64 1151.57,147.64 1230.32,226.38 1230.32,446.85 R54.1@1354.33,570.87
I27_5: J1.1 R61.1 | length 624.8
  Bottom Layer w10: J1.1@177.17,527.56 177.17,462.6 374.02,265.75 R61.1@655.51,265.75
I27_6: J1.3 R64.1 | length 609.1
  Bottom Layer w10: J1.3@177.17,627.56 177.17,590.55 403.54,364.17 R64.1@655.51,364.17
I27_7: J1.5 R67.1 | length 610.7
  Bottom Layer w10: J1.5@177.17,727.56 177.17,688.98 236.22,629.92 255.91,629.92 423.23,462.6 R67.1@655.51,462.6
I27_8: J1.7 R70.1 | length 612.3
  Bottom Layer w10: J1.7@177.17,827.56 177.17,787.4 232.23,732.34 271.6,732.34 442.91,561.02 R70.1@655.51,561.02
I27_D1: R80.5 U1.60 | length 1532.6
  Top Layer w6: R80.5@2087.87,216.8 2500.27,216.8 2775.59,492.13 3208.66,492.13 3385.83,669.29 U1.60@3433.07,669.29
I27_D1_R: R55.1 R80.4 U7.9 | length 459.1
  Top Layer w10: v1(1614.17,226.38) 1677.56,226.38 U7.9@1683.07,220.87 ; U7.9@1692.91,226.38 1702.49,216.8 R80.4@2017.72,216.8
  Bottom Layer w10: v1(1614.17,226.38) 1659.45,226.38 R55.1@1669.29,216.54
I27_D2: R80.6 U1.59 | length 1525.9
  Top Layer w6: R80.6@2087.87,252.8 2496.9,252.8 2765.75,521.65 3208.66,521.65 3374.57,687.56 3431.65,687.56 U1.59@3433.07,688.98
I27_D2_R: R56.1 R80.3 U7.11 | length 492.6
  Top Layer w10: v1(1614.17,324.8) 1679.13,324.8 U7.11@1683.07,320.87 1834.65,320.87 1902.71,252.8 R80.3@2017.72,252.8
  Bottom Layer w10: v1(1614.17,324.8) 1659.45,324.8 R56.1@1669.29,314.96
I27_D3: R80.7 U1.58 | length 1519.1
  Top Layer w6: R80.7@2087.87,288.8 2493.53,288.8 2755.91,551.18 3208.66,551.18 3366.14,708.66 U1.58@3433.07,708.66
I27_D3_R: R57.1 R80.2 U7.13 | length 514.3
  Top Layer w10: v1(1614.17,423.23) 1680.71,423.23 U7.13@1683.07,420.87 1823.23,420.87 1955.29,288.8 R80.2@2017.72,288.8
  Bottom Layer w10: v1(1614.17,423.23) R57.1@1669.29,423.23
I27_D4: R80.8 U1.57 | length 1512.3
  Top Layer w6: R80.8@2087.87,324.8 2490.16,324.8 2746.06,580.71 3208.66,580.71 3356.3,728.35 U1.57@3433.07,728.35
I27_D4_R: R58.1 R80.1 U7.15 | length 540.2
  Top Layer w10: v1(1614.17,521.65) 1682.28,521.65 U7.15@1683.07,520.87 1821.65,520.87 R80.1@2017.72,324.8
  Bottom Layer w10: v1(1614.17,521.65) R58.1@1669.29,521.65
I27_D5: R79.5 U1.56 | length 1459.2
  Top Layer w6: R79.5@2087.87,472.71 2598.69,472.71 2736.22,610.24 3208.66,610.24 3346.46,748.03 U1.56@3433.07,748.03
I27_D5_R: R71.1 R79.4 U8.9 | length 1572.1
  Top Layer w10: v1(915.35,216.54) 920.87,211.02 U8.9@984.25,211.02 1136.22,211.02 1200.79,275.59 1200.79,551.18 1289.37,639.76 1801.18,639.76 1968.24,472.71 R79.4@2017.72,472.71
  Bottom Layer w10: v1(915.35,216.54) 960.63,216.54 R71.1@970.47,206.69
I27_D6: R79.6 U1.55 | length 1452.5
  Top Layer w6: R79.6@2087.87,508.71 2595.32,508.71 2726.38,639.76 3208.66,639.76 3336.61,767.72 U1.55@3433.07,767.72
I27_D6_R: R72.1 R79.3 U8.11 | length 1496.8
  Top Layer w10: v1(915.35,314.96) 919.29,311.02 U8.11@984.25,311.02 1147.64,311.02 1181.1,344.49 1181.1,561.02 1279.53,659.45 1811.02,659.45 1961.76,508.71 R79.3@2017.72,508.71
  Bottom Layer w10: v1(915.35,314.96) 960.63,314.96 R72.1@970.47,305.12
I27_D7: R79.7 U1.54 | length 1445.7
  Top Layer w6: R79.7@2087.87,544.71 2591.95,544.71 2716.54,669.29 3208.66,669.29 3326.77,787.4 U1.54@3433.07,787.4
I27_D7_R: R73.1 R79.2 U8.13 | length 1394.4
  Top Layer w10: v1(915.35,413.39) 917.72,411.02 U8.13@984.25,411.02 1119.68,411.02 1161.42,452.76 1161.42,570.87 1269.69,679.13 1820.87,679.13 1955.29,544.71 R79.2@2017.72,544.71
  Bottom Layer w10: v1(915.35,413.39) R73.1@970.47,413.39
I27_D8: R79.8 U1.53 | length 1439
  Top Layer w6: R79.8@2087.87,580.71 2588.58,580.71 2706.69,698.82 3208.66,698.82 3316.93,807.09 U1.53@3433.07,807.09
I27_D8_R: R74.1 R79.1 U8.15 | length 1307.6
  Top Layer w10: v1(915.35,511.81) 916.14,511.02 U8.15@984.25,511.02 1111.42,511.02 1141.73,541.34 1141.73,580.71 1259.84,698.82 1830.71,698.82 1948.82,580.71 R79.1@2017.72,580.71
  Bottom Layer w10: v1(915.35,511.81) R74.1@970.47,511.81
JTAG_TCK: JP1.1 R3.1 U1.147 | length 2478.9
  Top Layer w10: v1(4625.98,1161.42) 4645.67,1181.1 U1.147@4795.28,1181.1
  Bottom Layer w10: JP1.1@3051.18,19.68 R3.1@3145.67,19.68 3238.19,112.2 3311.02,112.2 3415.35,216.54 3622.05,216.54 3838.58,433.07 3838.58,767.72 3937.01,866.14 4429.13,866.14 4625.98,1062.99 v1(4625.98,1161.42)
JTAG_TDI: JP1.9 R2.1 U1.155 | length 2430.7
  Top Layer w10: v1(4537.4,1220.47) 4655.51,1338.58 U1.155@4795.28,1338.58
  Bottom Layer w10: JP1.9@3051.18,419.68 3057.48,419.68 3110.24,472.44 3163.39,472.44 R2.1@3212.6,423.23 3740.16,423.23 3779.53,462.6 3779.53,797.24 3907.48,925.2 4360.24,925.2 4537.4,1102.36 v1(4537.4,1220.47)
JTAG_TDO: JP1.3 U1.149 | length 2608.9
  Top Layer w10: v1(4566.93,1200.79) 4586.61,1220.47 U1.149@4795.28,1220.47
  Bottom Layer w10: JP1.3@3051.18,119.68 3001.97,168.9 3001.97,246.06 3031.5,275.59 3622.05,275.59 3799.21,452.76 3799.21,787.4 3917.32,905.51 4389.76,905.51 4566.93,1082.68 v1(4566.93,1200.79)
JTAG_TMS: JP1.5 R1.1 U1.148 | length 2412.5
  Top Layer w10: v1(4596.46,1181.1) 4616.14,1200.79 U1.148@4795.28,1200.79
  Bottom Layer w10: JP1.5@3051.18,219.68 3142.52,219.68 R1.1@3145.67,216.54 3185.04,255.91 3631.89,255.91 3818.9,442.91 3818.9,777.56 3927.17,885.83 4409.45,885.83 4596.46,1072.83 v1(4596.46,1181.1)
NCE: JP2.6 R4.2 U1.33 | length 688.3
  Top Layer w10: v1(3346.46,1250) 3395.67,1200.79 U1.33@3433.07,1200.79
  Bottom Layer w10: R4.2@2858.27,1053.15 2948.03,1053.15 JP2.6@2951.18,1056.3 2997.24,1102.36 3061.02,1102.36 3100.39,1141.73 3100.39,1161.42 3110.24,1171.26 3159.45,1171.26 3238.19,1250 v1(3346.46,1250)
NCONFIG: JP2.5 R7.2 U1.26 | length 556.5
  Top Layer w10: v1(3375.98,1328.74) 3385.83,1338.58 U1.26@3433.07,1338.58
  Bottom Layer w10: JP2.5@3051.18,1056.3 3070.08,1056.3 R7.2@3145.67,1131.89 3234.25,1220.47 3366.14,1220.47 3375.98,1230.32 v1(3375.98,1328.74)
NCSO: JP2.8 U1.24 U2.1 | length 1106.4
  Top Layer w10: U2.1@2515.75,980.51 2691.54,1156.3 JP2.8@2951.18,1156.3 ; v1(3366.14,1407.48) 3395.67,1377.95 U1.24@3433.07,1377.95
  Bottom Layer w10: JP2.8@2951.18,1156.3 3005.51,1210.63 3129.92,1210.63 3326.77,1407.48 v1(3366.14,1407.48)
NetC61_1: C61.1 R81.1 | length 70.9
  Bottom Layer w10: C61.1@3005.91,3011.81 R81.1@3076.77,3011.81
NetC61_2: C61.2 D1.1 U9.2 U25.12 | length 813
  Top Layer w10: U9.2@2936.22,3236.61 2936.22,3156.3 2972.44,3120.08 3149.61,3120.08 U25.12@3346.46,3316.93
  Bottom Layer w10: U9.2@2936.22,3236.61 2938.98,3233.86 C61.2@2938.98,3011.81
NetC62_1: C62.1 R82.1 | length 70.9
  Bottom Layer w10: C62.1@2661.42,3011.81 R82.1@2732.28,3011.81
NetC62_2: C62.2 D2.1 U10.2 U25.13 | length 1180.6
  Top Layer w10: U10.2@2591.73,3236.61 2591.73,3126.77 2618.11,3100.39 3188.98,3100.39 U25.13@3356.3,3267.72
  Bottom Layer w10: U10.2@2591.73,3236.61 2594.49,3233.86 C62.2@2594.49,3011.81
NetC63_1: C63.1 R83.1 | length 70.9
  Bottom Layer w10: C63.1@2307.09,3011.81 R83.1@2377.95,3011.81
NetC63_2: C63.2 D3.1 U11.2 U25.14 | length 1528.5
  Top Layer w10: U11.2@2237.4,3236.61 2237.4,3107.09 2263.78,3080.71 3218.5,3080.71 U25.14@3346.46,3208.66
  Bottom Layer w10: U11.2@2237.4,3236.61 2240.16,3233.86 C63.2@2240.16,3011.81
NetC64_1: C64.1 R84.1 | length 70.9
  Bottom Layer w10: C64.1@1962.6,3011.81 R84.1@2033.46,3011.81
NetC64_2: C64.2 D4.1 U12.2 U25.15 | length 1870.9
  Top Layer w10: U12.2@1892.91,3236.61 1892.91,3103.54 1935.43,3061.02 3248.03,3061.02 U25.15@3346.46,3159.45
  Bottom Layer w10: U12.2@1892.91,3236.61 1895.67,3233.86 C64.2@1895.67,3011.81
NetC65_1: C65.1 R85.1 | length 70.9
  Bottom Layer w10: C65.1@1618.11,3011.81 R85.1@1688.98,3011.81
NetC65_2: C65.2 D5.1 U13.2 U25.16 | length 2242.6
  Top Layer w10: U13.2@1548.43,3236.61 1548.43,3083.86 1590.94,3041.34 3287.4,3041.34 3356.3,3110.24 U25.16@3366.14,3110.24
  Bottom Layer w10: U13.2@1548.43,3236.61 1551.18,3233.86 C65.2@1551.18,3011.81
NetC66_1: C66.1 R86.1 | length 70.9
  Bottom Layer w10: C66.1@1273.62,3011.81 R86.1@1344.49,3011.81
NetC66_2: C66.2 D6.1 U14.2 U25.17 | length 2575.5
  Top Layer w10: U14.2@1203.94,3236.61 1203.94,3103.54 1285.83,3021.65 3316.93,3021.65 U25.17@3366.14,3070.87
  Bottom Layer w10: U14.2@1203.94,3236.61 1206.69,3233.86 C66.2@1206.69,3011.81
NetC67_1: C67.1 R87.1 | length 70.9
  Bottom Layer w10: C67.1@929.13,3011.81 R87.1@1000,3011.81
NetC67_2: C67.2 D7.1 U15.2 U25.18 | length 2899.6
  Top Layer w10: U15.2@859.45,3236.61 859.45,3074.02 931.5,3001.97 3326.77,3001.97 U25.18@3336.61,3011.81
  Bottom Layer w10: U15.2@859.45,3236.61 862.2,3233.86 C67.2@862.2,3011.81
NetC68_1: C68.1 R88.1 | length 70.9
  Bottom Layer w10: C68.1@584.65,3011.81 R88.1@655.51,3011.81
NetC68_2: C68.2 D8.1 U16.2 U25.19 | length 3266.2
  Top Layer w10: U16.2@514.96,3236.61 514.96,3074.02 606.69,2982.28 3326.77,2982.28 U25.19@3346.46,2962.6
  Bottom Layer w10: U16.2@514.96,3236.61 517.72,3233.86 C68.2@517.72,3011.81
NetC71_1: C71.1 R91.1 | length 70.9
  Bottom Layer w10: C71.1@2996.06,2312.99 R91.1@3066.93,2312.99
NetC71_2: C71.2 D11.1 U17.2 U26.12 | length 817.1
  Top Layer w10: U17.2@2926.38,2537.8 2926.38,2467.32 2972.44,2421.26 3149.61,2421.26 U26.12@3346.46,2618.11
  Bottom Layer w10: U17.2@2926.38,2537.8 2929.13,2535.04 C71.2@2929.13,2312.99
NetC72_1: C72.1 R92.1 | length 70.9
  Bottom Layer w10: C72.1@2651.57,2312.99 R92.1@2722.44,2312.99
NetC72_2: C72.2 D12.1 U18.2 U26.13 | length 1188.7
  Top Layer w10: U18.2@2581.89,2537.8 2581.89,2437.8 2618.11,2401.57 3179.13,2401.57 U26.13@3356.3,2578.74
  Bottom Layer w10: U18.2@2581.89,2537.8 2584.65,2535.04 C72.2@2584.65,2312.99
NetC73_1: C73.1 R93.1 | length 70.9
  Bottom Layer w10: C73.1@2307.09,2312.99 R93.1@2377.95,2312.99
NetC73_2: C73.2 D13.1 U19.2 U26.14 | length 1521
  Top Layer w10: U19.2@2237.4,2537.8 2237.4,2427.95 2283.46,2381.89 3208.66,2381.89 U26.14@3346.46,2519.68
  Bottom Layer w10: U19.2@2237.4,2537.8 2240.16,2535.04 C73.2@2240.16,2312.99
NetC74_1: C74.1 R94.1 | length 70.9
  Bottom Layer w10: C74.1@1962.6,2312.99 R94.1@2033.46,2312.99
NetC74_2: C74.2 D14.1 U20.2 U26.15 | length 1867.2
  Top Layer w10: U20.2@1892.91,2537.8 1892.91,2418.11 1948.82,2362.2 3238.19,2362.2 U26.15@3346.46,2470.47
  Bottom Layer w10: U20.2@1892.91,2537.8 1895.67,2535.04 C74.2@1895.67,2312.99
NetC75_1: C75.1 R95.1 | length 82.3
  Bottom Layer w10: C75.1@1627.95,2322.83 R95.1@1698.82,2322.83 1702.76,2326.77 R95.1@1702.76,2332.68
NetC75_2: C75.2 D15.1 U21.2 U26.16 | length 2176.4
  Top Layer w10: U21.2@1558.27,2537.8 1558.27,2437.8 1653.54,2342.52 3267.72,2342.52 U26.16@3346.46,2421.26
  Bottom Layer w10: U21.2@1558.27,2537.8 1561.02,2535.04 C75.2@1561.02,2322.83
NetC76_1: C76.1 R96.1 | length 70.9
  Bottom Layer w10: C76.1@1273.62,2322.83 R96.1@1344.49,2322.83
NetC76_2: C76.2 D16.1 U22.2 U26.17 | length 2549.7
  Top Layer w10: U22.2@1203.94,2537.8 1203.94,2398.43 1279.53,2322.83 3297.24,2322.83 U26.17@3346.46,2372.05
  Bottom Layer w10: U22.2@1203.94,2537.8 1206.69,2535.04 C76.2@1206.69,2322.83
NetC77_1: C77.1 R97.1 | length 70.9
  Bottom Layer w10: C77.1@929.13,2322.83 R97.1@1000,2322.83
NetC77_2: C77.2 D17.1 U23.2 U26.18 | length 2913.1
  Top Layer w10: U23.2@859.45,2537.8 859.45,2418.11 974.41,2303.15 3359.06,2303.15 U26.18@3380.31,2324.41
  Bottom Layer w10: U23.2@859.45,2537.8 862.2,2535.04 C77.2@862.2,2322.83
NetC78_1: C78.1 R98.1 | length 74.8
  Bottom Layer w10: C78.1@584.65,2322.83 R98.1@655.51,2322.83 R98.1@659.45,2322.83
NetC78_2: C78.2 D18.1 U24.2 U26.19 | length 3260.7
  Top Layer w6: U24.2@514.96,2537.8 514.96,2418.11 649.61,2283.46 3371.26,2283.46 U26.19@3380.31,2274.41
  Bottom Layer w10: U24.2@514.96,2537.8 517.72,2535.04 C78.2@517.72,2322.83
NetC81_1: C81.1 Q1.2 R100.2 | length 168.4
  Top Layer w10: v1(5078.74,2214.57) Q1.2@5078.74,2258.93
  Bottom Layer w10: v1(5078.74,2214.57) C81.1@5078.74,2259.84 R100.2@5157.48,2259.84
NetC82_1: C82.1 Q2.2 R102.2 | length 156.2
  Top Layer w10: v1(5078.74,2549.21) Q2.2@5078.74,2588.58
  Bottom Layer w10: v1(5078.74,2549.21) 5078.74,2587.78 5155.76,2587.78 R102.2@5156.62,2588.64
NetC83_1: C83.1 Q3.2 R104.2 | length 169.6
  Top Layer w10: v1(4822.83,2214.57) 4822.83,2258.93 Q3.2@4823.69,2259.79
  Bottom Layer w10: v1(4822.83,2214.57) C83.1@4822.83,2259.84 R104.2@4901.57,2259.84
NetC84_1: C84.1 Q4.2 R106.2 | length 169.6
  Top Layer w10: v1(4822.83,2549.21) 4822.83,2593.57 Q4.2@4823.69,2594.43
  Bottom Layer w10: v1(4822.83,2549.21) C84.1@4822.83,2594.49 R106.2@4901.57,2594.49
